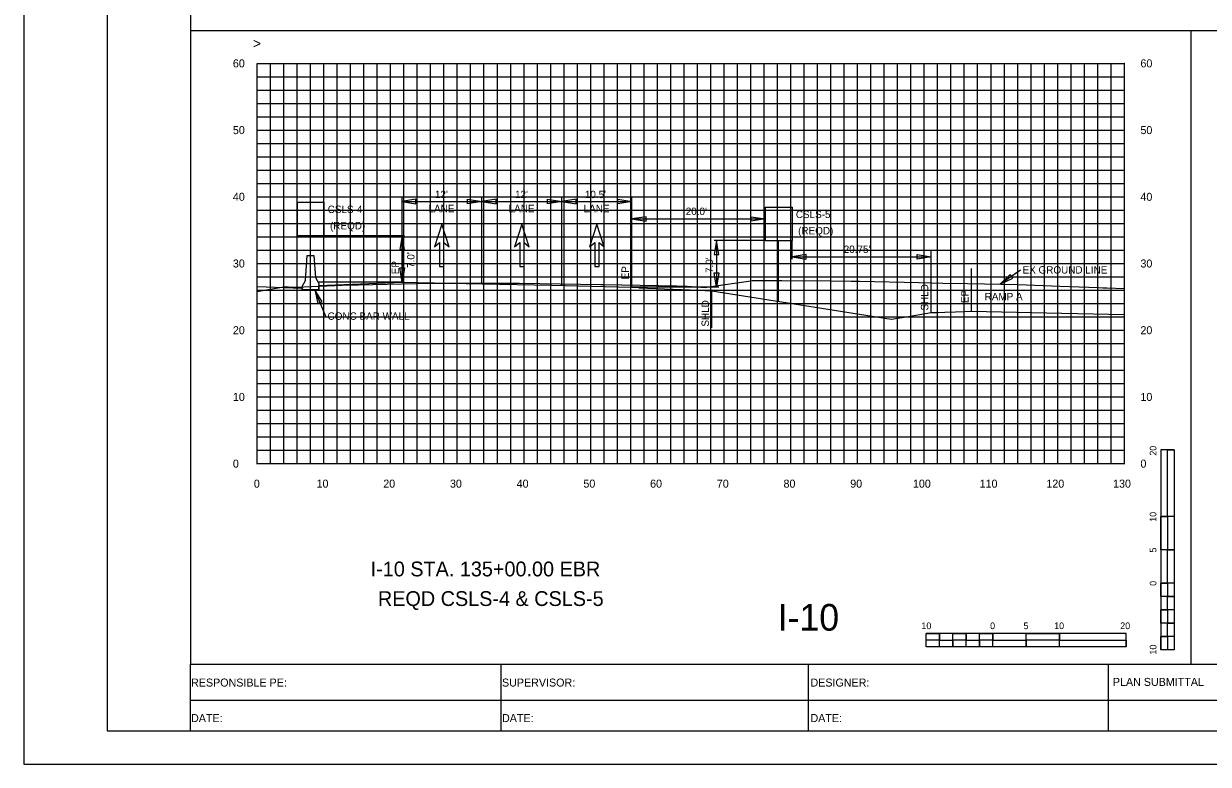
# Model space of a CAD drawing. Extents: x 2193008 to 2198143, y 1236112 to 1237864.
# Drawn here: x 2194512.7 to 2194690.3, y 1237118 to 1237229.1 of the extents above; entities that cross this region are included whole.
import ezdxf

# ---------------------------------------------------------------- set-up
doc = ezdxf.new("R2010")
doc.units = 0
for name, color, linetype in [('10', 7, 'Continuous'), ('3', 7, 'Continuous'), ('31', 7, 'Continuous'), ('60', 7, 'Continuous'), ('ANNO-TXT', 7, 'Continuous'), ('CL-CNST', 7, 'Continuous'), ('GSDIMS', 7, 'Continuous'), ('Level 1', 7, 'Continuous'), ('Level 28', 7, 'Continuous'), ('Level 33', 7, 'Continuous'), ('Level 55', 7, 'Continuous'), ('Level 61', 7, 'Continuous'), ('Level 62', 7, 'Continuous'), ('M-ROADS', 7, 'Continuous'), ('SHT-BDR', 7, 'Continuous'), ('SHT-BNDRY', 7, 'Continuous')]:
    doc.layers.add(name, color=color, linetype=linetype)

msp = doc.modelspace()

# ---------------------------------------------------------------- linework, layer by layer
msp.add_lwpolyline([(2194554.44, 1237189.66), (2194554.94, 1237190.57), (2194555.19, 1237194.33), (2194556.19, 1237194.33), (2194556.41, 1237191), (2194556.94, 1237190.09), (2194556.94, 1237189.18), (2194554.44, 1237189.18)], close=True)
at = {"layer": '3'}
for p, q in [((2194537.69, 1237228.05), (2194837.69, 1237228.05)), ((2194687.69, 1237133.05), (2194687.69, 1237228.05)), ((2194569.4, 1237190.33), (2194569.4, 1237203.07)), ((2194581.36, 1237190.07), (2194581.36, 1237203.07)), ((2194593.36, 1237189.8), (2194593.36, 1237203.07)), ((2194603.86, 1237189.57), (2194603.86, 1237203.07)), ((2194555.69, 1237194.33), (2194555.69, 1237197.33)), ((2194625.86, 1237187.43), (2194625.86, 1237196.57)), ((2194627.86, 1237193.75), (2194627.86, 1237196.57)), ((2194654.79, 1237185.99), (2194654.79, 1237192.38)), ((2194662.09, 1237192.1), (2194659.04, 1237190.01)), ((2194557.97, 1237185.16), (2194556.31, 1237189.18))]:
    msp.add_line(p, q, dxfattribs=at)
at = {"layer": '60'}
for p, q in [((2194547.69, 1237163.11), (2194547.69, 1237223.11)), ((2194677.69, 1237163.11), (2194677.69, 1237223.11)), ((2194677.75, 1237223.11), (2194677.69, 1237223.11)), ((2194677.75, 1237213.11), (2194677.69, 1237213.11)), ((2194677.75, 1237203.11), (2194677.69, 1237203.11)), ((2194677.75, 1237193.11), (2194677.69, 1237193.11)), ((2194677.75, 1237183.11), (2194677.69, 1237183.11)), ((2194677.75, 1237173.11), (2194677.69, 1237173.11)), ((2194547.69, 1237163.05), (2194547.69, 1237163.11)), ((2194547.69, 1237163.11), (2194677.69, 1237163.11)), ((2194557.69, 1237163.05), (2194557.69, 1237163.11)), ((2194567.69, 1237163.05), (2194567.69, 1237163.11)), ((2194577.69, 1237163.05), (2194577.69, 1237163.11)), ((2194587.69, 1237163.05), (2194587.69, 1237163.11)), ((2194597.69, 1237163.05), (2194597.69, 1237163.11)), ((2194607.69, 1237163.05), (2194607.69, 1237163.11)), ((2194617.69, 1237163.05), (2194617.69, 1237163.11)), ((2194627.69, 1237163.05), (2194627.69, 1237163.11)), ((2194637.69, 1237163.05), (2194637.69, 1237163.11)), ((2194647.69, 1237163.05), (2194647.69, 1237163.11)), ((2194657.69, 1237163.05), (2194657.69, 1237163.11)), ((2194667.69, 1237163.05), (2194667.69, 1237163.11)), ((2194677.69, 1237163.05), (2194677.69, 1237163.11)), ((2194677.75, 1237163.11), (2194677.69, 1237163.11))]:
    msp.add_line(p, q, dxfattribs=at)
at = {"layer": 'CL-CNST'}
for points in [[(2194547.69, 1237189.67), (2194554.44, 1237189.4), (2194554.44, 1237189.18), (2194556.94, 1237189.18), (2194556.94, 1237189.83), (2194569.4, 1237190.33), (2194581.4, 1237190.07), (2194591.86, 1237189.84), (2194603.86, 1237189.57), (2194604.86, 1237189.53), (2194604.93, 1237189.46), (2194613.86, 1237189.1), (2194615.86, 1237189.02), (2194642.71, 1237184.76)], [(2194642.71, 1237184.76), (2194645.04, 1237185.14), (2194648.74, 1237185.75), (2194649.55, 1237185.78), (2194650.77, 1237185.83), (2194652.39, 1237185.89), (2194654.79, 1237185.99), (2194668.32, 1237185.68), (2194677.69, 1237185.46)]]:
    msp.add_lwpolyline(points, dxfattribs=at)
at = {"layer": 'GSDIMS'}
for p, q in [((2194553.69, 1237202.33), (2194553.69, 1237197.33)), ((2194553.69, 1237202.33), (2194557.69, 1237202.33)), ((2194557.69, 1237202.33), (2194557.69, 1237197.33)), ((2194569.36, 1237202.41), (2194581.36, 1237202.41)), ((2194581.36, 1237202.41), (2194593.36, 1237202.41)), ((2194593.36, 1237202.41), (2194603.86, 1237202.41)), ((2194623.86, 1237201.57), (2194623.86, 1237196.57)), ((2194623.86, 1237201.57), (2194627.86, 1237201.57)), ((2194627.86, 1237201.57), (2194627.86, 1237196.57)), ((2194553.69, 1237197.33), (2194557.69, 1237197.33)), ((2194557.69, 1237197.33), (2194569.75, 1237197.33)), ((2194569.4, 1237197.33), (2194569.4, 1237190.33)), ((2194623.86, 1237196.57), (2194616.18, 1237196.57)), ((2194616.53, 1237196.57), (2194616.53, 1237189.57)), ((2194623.86, 1237196.57), (2194627.86, 1237196.57)), ((2194648.74, 1237185.75), (2194648.74, 1237194.96)), ((2194569.4, 1237190.33), (2194556.8, 1237190.33)), ((2194616.88, 1237189.57), (2194603.86, 1237189.57)), ((2194615.86, 1237183.47), (2194615.86, 1237189.02))]:
    msp.add_line(p, q, dxfattribs=at)
for points in [[(2194569.36, 1237202.41), (2194571.49, 1237202.06), (2194571.49, 1237202.76)], [(2194581.36, 1237202.41), (2194579.23, 1237202.06), (2194579.23, 1237202.76)], [(2194581.36, 1237202.41), (2194583.49, 1237202.06), (2194583.49, 1237202.76)], [(2194593.36, 1237202.41), (2194591.23, 1237202.06), (2194591.23, 1237202.76)], [(2194593.36, 1237202.41), (2194595.49, 1237202.06), (2194595.49, 1237202.76)], [(2194603.86, 1237202.41), (2194601.73, 1237202.06), (2194601.73, 1237202.76)], [(2194603.86, 1237199.79), (2194605.99, 1237199.44), (2194605.99, 1237200.13)], [(2194623.86, 1237199.79), (2194621.73, 1237199.44), (2194621.73, 1237200.13)], [(2194569.4, 1237197.33), (2194569.05, 1237195.2), (2194569.75, 1237195.2)], [(2194616.53, 1237196.57), (2194616.18, 1237194.45), (2194616.88, 1237194.45)], [(2194627.86, 1237194.1), (2194629.99, 1237193.75), (2194629.99, 1237194.44)], [(2194648.74, 1237194.1), (2194646.61, 1237193.75), (2194646.61, 1237194.44)], [(2194569.4, 1237190.33), (2194569.05, 1237192.46), (2194569.75, 1237192.46)], [(2194616.53, 1237189.57), (2194616.18, 1237191.7), (2194616.88, 1237191.7)], [(2194659.04, 1237190.01), (2194660.98, 1237190.91), (2194660.57, 1237191.48)], [(2194556.31, 1237189.18), (2194556.79, 1237187.1), (2194557.44, 1237187.38)]]:
    msp.add_lwpolyline(points, close=True, dxfattribs=at)
at = {"layer": 'Level 1'}
for p, q in [((2194683.16, 1237165.19), (2194683.16, 1237135.19)), ((2194685.16, 1237165.19), (2194683.16, 1237165.19)), ((2194685.16, 1237165.19), (2194685.16, 1237155.19)), ((2194685.16, 1237165.19), (2194685.16, 1237135.19)), ((2194684.16, 1237155.19), (2194683.16, 1237155.19)), ((2194685.16, 1237155.19), (2194683.16, 1237155.19)), ((2194684.16, 1237155.19), (2194684.16, 1237150.19)), ((2194685.16, 1237150.19), (2194683.16, 1237150.19)), ((2194685.16, 1237150.19), (2194684.16, 1237150.19)), ((2194685.16, 1237150.19), (2194685.16, 1237145.19)), ((2194684.16, 1237145.19), (2194683.16, 1237145.19)), ((2194685.16, 1237145.19), (2194683.16, 1237145.19)), ((2194684.16, 1237145.19), (2194684.16, 1237143.19)), ((2194685.16, 1237143.19), (2194684.16, 1237143.19)), ((2194685.16, 1237143.19), (2194685.16, 1237141.19)), ((2194684.16, 1237141.19), (2194683.16, 1237141.19)), ((2194684.16, 1237141.19), (2194684.16, 1237139.19)), ((2194685.16, 1237139.19), (2194684.16, 1237139.19)), ((2194685.16, 1237139.19), (2194685.16, 1237137.19)), ((2194677.96, 1237137.63), (2194647.96, 1237137.63)), ((2194647.96, 1237135.63), (2194647.96, 1237137.63)), ((2194649.96, 1237136.63), (2194647.96, 1237136.63)), ((2194649.96, 1237136.63), (2194649.96, 1237137.63)), ((2194651.96, 1237135.63), (2194651.96, 1237136.63)), ((2194653.96, 1237136.63), (2194651.96, 1237136.63)), ((2194653.96, 1237136.63), (2194653.96, 1237137.63)), ((2194655.96, 1237135.63), (2194655.96, 1237136.63)), ((2194657.96, 1237136.63), (2194655.96, 1237136.63)), ((2194657.96, 1237136.63), (2194657.96, 1237137.63)), ((2194657.96, 1237135.63), (2194657.96, 1237137.63)), ((2194662.96, 1237135.63), (2194662.96, 1237137.63)), ((2194662.96, 1237135.63), (2194662.96, 1237136.63)), ((2194667.96, 1237136.63), (2194662.96, 1237136.63)), ((2194667.96, 1237136.63), (2194667.96, 1237137.63)), ((2194667.96, 1237135.63), (2194667.96, 1237137.63)), ((2194677.96, 1237135.63), (2194677.96, 1237137.63)), ((2194684.16, 1237137.19), (2194683.16, 1237137.19)), ((2194684.16, 1237137.19), (2194684.16, 1237135.19)), ((2194677.96, 1237135.63), (2194647.96, 1237135.63)), ((2194651.96, 1237135.63), (2194649.96, 1237135.63)), ((2194655.96, 1237135.63), (2194653.96, 1237135.63)), ((2194662.96, 1237135.63), (2194657.96, 1237135.63)), ((2194677.96, 1237135.63), (2194667.96, 1237135.63)), ((2194685.16, 1237135.19), (2194683.16, 1237135.19))]:
    msp.add_line(p, q, dxfattribs=at)
for points in [[(2194684.16, 1237155.19), (2194684.16, 1237165.19), (2194685.16, 1237165.19), (2194685.16, 1237155.19)], [(2194683.16, 1237150.19), (2194683.16, 1237155.19), (2194684.16, 1237155.19), (2194684.16, 1237150.19)], [(2194684.16, 1237145.19), (2194684.16, 1237150.19), (2194685.16, 1237150.19), (2194685.16, 1237145.19)], [(2194683.16, 1237143.19), (2194683.16, 1237145.19), (2194684.16, 1237145.19), (2194684.16, 1237143.19)], [(2194684.16, 1237141.19), (2194684.16, 1237143.19), (2194685.16, 1237143.19), (2194685.16, 1237141.19)], [(2194683.16, 1237139.19), (2194683.16, 1237141.19), (2194684.16, 1237141.19), (2194684.16, 1237139.19)], [(2194684.16, 1237137.19), (2194684.16, 1237139.19), (2194685.16, 1237139.19), (2194685.16, 1237137.19)], [(2194647.96, 1237137.63), (2194649.96, 1237137.63), (2194649.96, 1237136.63), (2194647.96, 1237136.63)], [(2194649.96, 1237136.63), (2194651.96, 1237136.63), (2194651.96, 1237135.63), (2194649.96, 1237135.63)], [(2194651.96, 1237137.63), (2194653.96, 1237137.63), (2194653.96, 1237136.63), (2194651.96, 1237136.63)], [(2194653.96, 1237136.63), (2194655.96, 1237136.63), (2194655.96, 1237135.63), (2194653.96, 1237135.63)], [(2194655.96, 1237137.63), (2194657.96, 1237137.63), (2194657.96, 1237136.63), (2194655.96, 1237136.63)], [(2194657.96, 1237136.63), (2194662.96, 1237136.63), (2194662.96, 1237135.63), (2194657.96, 1237135.63)], [(2194662.96, 1237137.63), (2194667.96, 1237137.63), (2194667.96, 1237136.63), (2194662.96, 1237136.63)], [(2194667.96, 1237136.63), (2194677.96, 1237136.63), (2194677.96, 1237135.63), (2194667.96, 1237135.63)], [(2194683.16, 1237135.19), (2194683.16, 1237137.19), (2194684.16, 1237137.19), (2194684.16, 1237135.19)]]:
    msp.add_lwpolyline(points, close=True, dxfattribs=at)
at = {"layer": 'Level 28'}
for p, q in [((2194575.36, 1237199.01), (2194574.27, 1237195.61)), ((2194576.45, 1237195.61), (2194575.36, 1237199.01)), ((2194587.36, 1237199.01), (2194586.27, 1237195.61)), ((2194588.45, 1237195.61), (2194587.36, 1237199.01)), ((2194598.61, 1237199.01), (2194597.52, 1237195.61)), ((2194599.7, 1237195.61), (2194598.61, 1237199.01)), ((2194574.27, 1237195.61), (2194575.04, 1237196.25)), ((2194575.04, 1237196.25), (2194575.04, 1237192.68)), ((2194575.69, 1237192.68), (2194575.69, 1237196.25)), ((2194575.69, 1237196.25), (2194576.45, 1237195.61)), ((2194586.27, 1237195.61), (2194587.04, 1237196.25)), ((2194587.04, 1237196.25), (2194587.04, 1237192.68)), ((2194587.69, 1237192.68), (2194587.69, 1237196.25)), ((2194587.69, 1237196.25), (2194588.45, 1237195.61)), ((2194597.52, 1237195.61), (2194598.29, 1237196.25)), ((2194598.29, 1237196.25), (2194598.29, 1237192.68)), ((2194598.94, 1237192.68), (2194598.94, 1237196.25)), ((2194598.94, 1237196.25), (2194599.7, 1237195.61)), ((2194575.04, 1237192.68), (2194575.69, 1237192.68)), ((2194587.04, 1237192.68), (2194587.69, 1237192.68)), ((2194598.29, 1237192.68), (2194598.94, 1237192.68))]:
    msp.add_line(p, q, dxfattribs=at)
at = {"layer": 'Level 61'}
for p, q in [((2194603.86, 1237199.79), (2194623.86, 1237199.79)), ((2194627.86, 1237194.1), (2194648.74, 1237194.1))]:
    msp.add_line(p, q, dxfattribs=at)
at = {"layer": 'Level 62'}
for p, q in [((2194547.69, 1237223.11), (2194677.69, 1237223.11)), ((2194549.69, 1237163.11), (2194549.69, 1237223.11)), ((2194551.69, 1237163.11), (2194551.69, 1237223.11)), ((2194553.69, 1237163.11), (2194553.69, 1237223.11)), ((2194555.69, 1237163.11), (2194555.69, 1237223.11)), ((2194557.69, 1237163.11), (2194557.69, 1237223.11)), ((2194559.69, 1237163.11), (2194559.69, 1237223.11)), ((2194561.69, 1237163.11), (2194561.69, 1237223.11)), ((2194563.69, 1237163.11), (2194563.69, 1237223.11)), ((2194565.69, 1237163.11), (2194565.69, 1237223.11)), ((2194567.69, 1237163.11), (2194567.69, 1237223.11)), ((2194569.69, 1237163.11), (2194569.69, 1237223.11)), ((2194571.69, 1237163.11), (2194571.69, 1237223.11)), ((2194573.69, 1237163.11), (2194573.69, 1237223.11)), ((2194575.69, 1237163.11), (2194575.69, 1237223.11)), ((2194577.69, 1237163.11), (2194577.69, 1237223.11)), ((2194579.69, 1237163.11), (2194579.69, 1237223.11)), ((2194581.69, 1237163.11), (2194581.69, 1237223.11)), ((2194583.69, 1237163.11), (2194583.69, 1237223.11)), ((2194585.69, 1237163.11), (2194585.69, 1237223.11)), ((2194587.69, 1237163.11), (2194587.69, 1237223.11)), ((2194589.69, 1237163.11), (2194589.69, 1237223.11)), ((2194591.69, 1237163.11), (2194591.69, 1237223.11)), ((2194593.69, 1237163.11), (2194593.69, 1237223.11)), ((2194595.69, 1237163.11), (2194595.69, 1237223.11)), ((2194597.69, 1237163.11), (2194597.69, 1237223.11)), ((2194599.69, 1237163.11), (2194599.69, 1237223.11)), ((2194601.69, 1237163.11), (2194601.69, 1237223.11)), ((2194603.69, 1237163.11), (2194603.69, 1237223.11)), ((2194605.69, 1237163.11), (2194605.69, 1237223.11)), ((2194607.69, 1237163.11), (2194607.69, 1237223.11)), ((2194609.69, 1237163.11), (2194609.69, 1237223.11)), ((2194611.69, 1237163.11), (2194611.69, 1237223.11)), ((2194613.69, 1237163.11), (2194613.69, 1237223.11)), ((2194615.69, 1237163.11), (2194615.69, 1237223.11)), ((2194617.69, 1237163.11), (2194617.69, 1237223.11)), ((2194619.69, 1237163.11), (2194619.69, 1237223.11)), ((2194621.69, 1237163.11), (2194621.69, 1237223.11)), ((2194623.69, 1237163.11), (2194623.69, 1237223.11)), ((2194625.69, 1237163.11), (2194625.69, 1237223.11)), ((2194627.69, 1237163.11), (2194627.69, 1237223.11)), ((2194629.69, 1237163.11), (2194629.69, 1237223.11)), ((2194631.69, 1237163.11), (2194631.69, 1237223.11)), ((2194633.69, 1237163.11), (2194633.69, 1237223.11)), ((2194635.69, 1237163.11), (2194635.69, 1237223.11)), ((2194637.69, 1237163.11), (2194637.69, 1237223.11)), ((2194639.69, 1237163.11), (2194639.69, 1237223.11)), ((2194641.69, 1237163.11), (2194641.69, 1237223.11)), ((2194643.69, 1237163.11), (2194643.69, 1237223.11)), ((2194645.69, 1237163.11), (2194645.69, 1237223.11)), ((2194647.69, 1237163.11), (2194647.69, 1237223.11)), ((2194649.69, 1237163.11), (2194649.69, 1237223.11)), ((2194651.69, 1237163.11), (2194651.69, 1237223.11)), ((2194653.69, 1237163.11), (2194653.69, 1237223.11)), ((2194655.69, 1237163.11), (2194655.69, 1237223.11)), ((2194657.69, 1237163.11), (2194657.69, 1237223.11)), ((2194659.69, 1237163.11), (2194659.69, 1237223.11)), ((2194661.69, 1237163.11), (2194661.69, 1237223.11)), ((2194663.69, 1237163.11), (2194663.69, 1237223.11)), ((2194665.69, 1237163.11), (2194665.69, 1237223.11)), ((2194667.69, 1237163.11), (2194667.69, 1237223.11)), ((2194669.69, 1237163.11), (2194669.69, 1237223.11)), ((2194671.69, 1237163.11), (2194671.69, 1237223.11)), ((2194673.69, 1237163.11), (2194673.69, 1237223.11)), ((2194675.69, 1237163.11), (2194675.69, 1237223.11)), ((2194677.69, 1237163.11), (2194677.69, 1237223.11)), ((2194547.69, 1237221.11), (2194677.69, 1237221.11)), ((2194547.69, 1237219.11), (2194677.69, 1237219.11)), ((2194547.69, 1237217.11), (2194677.69, 1237217.11)), ((2194547.69, 1237215.11), (2194677.69, 1237215.11)), ((2194547.69, 1237213.11), (2194677.69, 1237213.11)), ((2194547.69, 1237211.11), (2194677.69, 1237211.11)), ((2194547.69, 1237209.11), (2194677.69, 1237209.11)), ((2194547.69, 1237207.11), (2194677.69, 1237207.11)), ((2194547.69, 1237205.11), (2194677.69, 1237205.11)), ((2194547.69, 1237203.11), (2194677.69, 1237203.11)), ((2194547.69, 1237201.11), (2194677.69, 1237201.11)), ((2194547.69, 1237199.11), (2194677.69, 1237199.11)), ((2194547.69, 1237197.11), (2194677.69, 1237197.11)), ((2194547.69, 1237195.11), (2194677.69, 1237195.11)), ((2194547.69, 1237193.11), (2194677.69, 1237193.11)), ((2194547.69, 1237191.11), (2194677.69, 1237191.11)), ((2194547.69, 1237189.11), (2194677.69, 1237189.11)), ((2194547.69, 1237187.11), (2194677.69, 1237187.11)), ((2194547.69, 1237185.11), (2194677.69, 1237185.11)), ((2194547.69, 1237183.11), (2194677.69, 1237183.11)), ((2194547.69, 1237181.11), (2194677.69, 1237181.11)), ((2194547.69, 1237179.11), (2194677.69, 1237179.11)), ((2194547.69, 1237177.11), (2194677.69, 1237177.11)), ((2194547.69, 1237175.11), (2194677.69, 1237175.11)), ((2194547.69, 1237173.11), (2194677.69, 1237173.11)), ((2194547.69, 1237171.11), (2194677.69, 1237171.11)), ((2194547.69, 1237169.11), (2194677.69, 1237169.11)), ((2194547.69, 1237167.11), (2194677.69, 1237167.11)), ((2194547.69, 1237165.11), (2194677.69, 1237165.11)), ((2194547.69, 1237163.11), (2194677.69, 1237163.11))]:
    msp.add_line(p, q, dxfattribs=at)
msp.add_lwpolyline([(2194512.69, 1237118.04), (2194852.69, 1237118.04), (2194852.69, 1237338.04), (2194512.69, 1237338.04)], close=True, dxfattribs=at)
at = {"layer": 'M-ROADS'}
msp.add_lwpolyline([(2194547.69, 1237188.9), (2194551.96, 1237189.66), (2194552.88, 1237189.56), (2194552.96, 1237189.55), (2194553.53, 1237189.57), (2194561.65, 1237189.9), (2194561.87, 1237189.9), (2194562.9, 1237189.93), (2194573.65, 1237190.15), (2194574.77, 1237190.18), (2194575.01, 1237190.18), (2194586.68, 1237190.16), (2194587.02, 1237190.15), (2194599.21, 1237189.96), (2194599.58, 1237189.95), (2194610.59, 1237189.76), (2194611.69, 1237189.71), (2194611.83, 1237189.7), (2194612.16, 1237189.69), (2194614.85, 1237189.53), (2194615.37, 1237189.61), (2194621.69, 1237190.5), (2194621.91, 1237190.54), (2194621.93, 1237190.54), (2194626.33, 1237190.58), (2194633.7, 1237190.51), (2194636.74, 1237190.48), (2194637.17, 1237190.46), (2194637.99, 1237190.45), (2194646.93, 1237190.25), (2194650.45, 1237190.17), (2194654.15, 1237190.1), (2194661.75, 1237189.96), (2194667.99, 1237189.72), (2194673.82, 1237189.5), (2194674.43, 1237189.47), (2194675.06, 1237189.44), (2194677.69, 1237189.35)], dxfattribs=at)
at = {"layer": 'SHT-BDR'}
msp.add_lwpolyline([(2194537.69, 1237133.05), (2194837.69, 1237133.05), (2194837.69, 1237323.05), (2194537.69, 1237323.05)], close=True, dxfattribs=at)
at = {"layer": 'SHT-BNDRY'}
for p, q in [((2194537.69, 1237123.04), (2194537.69, 1237133.05)), ((2194584.21, 1237133.05), (2194584.21, 1237123.04)), ((2194630.35, 1237123.04), (2194630.35, 1237133.05)), ((2194675.28, 1237123.04), (2194675.28, 1237133.05)), ((2194537.69, 1237127.65), (2194693.32, 1237127.65))]:
    msp.add_line(p, q, dxfattribs=at)
msp.add_lwpolyline([(2194525.19, 1237123.04), (2194847.69, 1237123.04), (2194847.69, 1237333.04), (2194525.19, 1237333.04)], close=True, dxfattribs=at)

# ---------------------------------------------------------------- texts
at = {"layer": '10'}
for s, p in [('0', (2194547.19, 1237159.51)), ('10', (2194556.59, 1237159.51)), ('20', (2194566.59, 1237159.51)), ('30', (2194576.59, 1237159.51)), ('40', (2194586.59, 1237159.51)), ('50', (2194596.59, 1237159.51)), ('60', (2194606.59, 1237159.51)), ('70', (2194616.59, 1237159.51)), ('80', (2194626.59, 1237159.51)), ('90', (2194636.59, 1237159.51)), ('100', (2194645.99, 1237159.51)), ('110', (2194655.99, 1237159.51)), ('120', (2194665.99, 1237159.51)), ('130', (2194675.99, 1237159.51))]:
    msp.add_text(s, height=1.2, dxfattribs=at).set_placement(p)
at = {"layer": '31'}
for s, p in [('60', (2194544.05, 1237222.51)), ('60', (2194680.09, 1237222.51)), ('50', (2194544.05, 1237212.51)), ('50', (2194680.09, 1237212.51)), ('40', (2194544.05, 1237202.51)), ('40', (2194680.09, 1237202.51)), ('30', (2194544.05, 1237192.51)), ('30', (2194680.09, 1237192.51)), ('20', (2194544.05, 1237182.51)), ('20', (2194680.09, 1237182.51)), ('10', (2194544.05, 1237172.51)), ('10', (2194680.09, 1237172.51)), ('0', (2194544.05, 1237162.51)), ('0', (2194680.09, 1237162.51))]:
    msp.add_text(s, height=1.2, dxfattribs=at).set_placement(p)
at = {"layer": '60'}
msp.add_text('>', height=1.5, dxfattribs=at).set_placement((2194547.08, 1237225.36))
at = {"layer": 'ANNO-TXT'}
for s, p in [('RESPONSIBLE PE:', (2194537.78, 1237129.69)), ('SUPERVISOR:', (2194584.39, 1237129.69)), ('DESIGNER:', (2194630.63, 1237129.69)), ('PLAN SUBMITTAL', (2194675.96, 1237129.79)), ('DATE:', (2194537.78, 1237124.37)), ('DATE:', (2194584.39, 1237124.37)), ('DATE:', (2194630.63, 1237124.37))]:
    msp.add_text(s, height=1.2, rotation=360, dxfattribs=at).set_placement(p)
at = {"layer": 'Level 1'}
for s, height, rotation, p in [('20', 0.999, 90.0572, (2194682.49, 1237164.3)), ('10', 0.999, 90.0572, (2194682.49, 1237154.39)), ('5', 1, 90.0572, (2194682.49, 1237149.78)), ('0', 1, 90.0572, (2194682.49, 1237144.79)), ('10', 0.999, 0.0572, (2194647.26, 1237138.3)), ('0', 1, 0.0572, (2194657.56, 1237138.3)), ('5', 0.999, 0.0572, (2194662.56, 1237138.3)), ('10', 0.999, 0.0572, (2194667.16, 1237138.3)), ('20', 0.999, 0.0572, (2194677.06, 1237138.3)), ('10', 0.999, 90.0572, (2194682.49, 1237134.49))]:
    msp.add_text(s, height=height, rotation=rotation, dxfattribs=at).set_placement(p)
at = {"layer": 'Level 33'}
msp.add_text('I-10', height=3.998, rotation=360, dxfattribs=at).set_placement((2194625.71, 1237138.07))
at = {"layer": 'Level 55'}
for s, height, p in [("12'", 1.11, (2194574.34, 1237202.91)), ("12'", 1.11, (2194586.34, 1237202.91)), ("10.5'", 1.11, (2194596.81, 1237202.91)), ('LANE', 1.11, (2194573.38, 1237200.8)), ('LANE', 1.11, (2194585.38, 1237200.8)), ('LANE', 1.11, (2194596.63, 1237200.8)), ("20.0'", 1.11, (2194611.93, 1237200.38)), ("20.75'", 1.11, (2194635.61, 1237194.69)), ('EX GROUND LINE', 1.1105, (2194662.42, 1237191.6)), ('RAMP A', 1.11, (2194656.74, 1237187.6)), ('CONC BAR WALL', 1.1105, (2194558.24, 1237184.67)), ('I-10 STA. 135+00.00 EBR ', 2.2209, (2194564.7, 1237146.21)), ('REQD CSLS-4 & CSLS-5', 2.2209, (2194565.79, 1237141.77))]:
    msp.add_text(s, height=height, dxfattribs=at).set_placement(p)
for s, rotation, p in [('CSLS-4', 360, (2194558.26, 1237200.68)), ('CSLS-5', 360, (2194628.44, 1237199.92)), ('(REQD)', 360, (2194558.61, 1237198.23)), ('(REQD)', 360, (2194628.78, 1237197.48)), ("7.0'", 90, (2194571.27, 1237192.45)), ('EP', 90, (2194568.95, 1237191.5)), ("7.0'", 90, (2194616.03, 1237191.69)), ('EP', 90, (2194603.41, 1237190.74)), ('SHLD', 90, (2194648.29, 1237186.06)), ('EP', 90, (2194654.34, 1237187.17)), ('SHLD', 90, (2194615.41, 1237183.65))]:
    msp.add_text(s, height=1.11, rotation=rotation, dxfattribs=at).set_placement(p)

doc.saveas('drawing.dxf')
